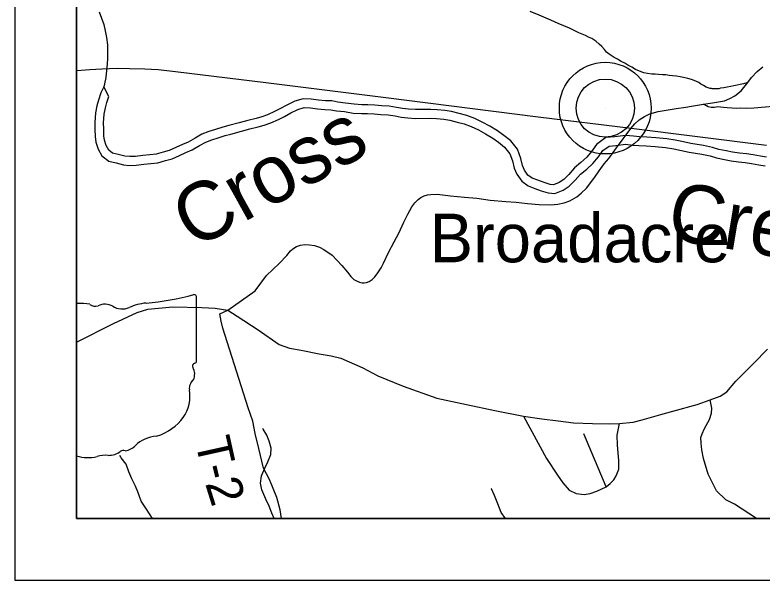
# Model space of a CAD drawing. Extents: x 0 to 34, y 0 to 22.
# Drawn here: x 2 to 3.211, y 14 to 14.917 of the extents above; entities that cross this region are included whole.
import ezdxf

# ---------------------------------------------------------------- set-up
doc = ezdxf.new("R2010")
doc.units = 0
for name, color, linetype in [('GM_X_Corporation', 7, 'Continuous'), ('GM_X_Corporation_Text', 7, 'Continuous'), ('GM_X_County_Road', 7, 'Continuous'), ('GM_X_Minor_River', 7, 'Continuous'), ('GM_X_Minor_River_Text', 7, 'Continuous'), ('GM_X_Rail_Line', 7, 'Continuous'), ('GM_X_State_Location', 7, 'Continuous'), ('GM_X_State_Route', 7, 'Continuous'), ('GM_X_Township_Road', 7, 'Continuous'), ('GM_X_Township_Road_Text', 7, 'Continuous'), ('GM_X_Unincorporated', 7, 'Continuous'), ('GM_X_Unincorporated_Location', 7, 'Continuous'), ('GM_X_Unincorporated_Text', 7, 'Continuous'), ('SH_Data', 7, 'Continuous')]:
    doc.layers.add(name, color=color, linetype=linetype)

msp = doc.modelspace()

# ---------------------------------------------------------------- linework, layer by layer
at = {"layer": 'GM_X_Corporation'}
msp.add_lwpolyline([(2.1, 15.7148), (2.1, 14.1), (4.5503, 14.1), (4.5507, 14.1138), (4.5505, 14.2449), (4.5614, 14.6695), (4.5616, 14.6767), (4.5617, 14.6817), (4.5685, 14.9157), (4.5738, 15.1325), (4.5873, 15.6794), (4.2138, 15.6834), (3.9277, 15.6898), (3.3171, 15.6975), (2.4078, 15.7088)], close=True, dxfattribs=at)
at = {"layer": 'GM_X_Corporation_Text'}
msp.add_line((2.1, 14.4488), (2.1, 14.2016), dxfattribs=at)
msp.add_lwpolyline([(2.2942, 14.3551), (2.2942, 14.3551), (2.2943, 14.3551), (2.2943, 14.4599)], dxfattribs=at)
for centre, major_axis, start_param, end_param in [((2.1769, 14.7276), (0.3495, 0), 4.814394, 5.042369), ((2.2906, 14.4602), (0.00367, 0), 6.197627, 7.989034), ((2.0997, 14.3425), (0.133, 0), 1.404758, 1.568575), ((2.1299, 14.4528), (0.0107, 0), 3.836095, 5.185415), ((2.1456, 14.4297), (0.0222, 0), 0.950623, 2.079405), ((2.1742, 14.4614), (0.0267, 0), 4.08156, 5.145723), ((2.2214, 14.3937), (0.0703, 0), 1.699012, 2.107814), ((2.2903, 14.3547), (0.00393, 0), 5.05454, 6.418171), ((2.2934, 14.3474), (0.00568, 0), 1.883978, 3.671073), ((2.2573, 14.3342), (0.0341, 0), 5.934695, 6.695948), ((2.3074, 14.3113), (0.0248, 0), 2.387724, 3.262537), ((2.1964, 14.298), (0.0874, 0), 5.101753, 6.440018), ((2.2333, 14.1951), (0.0479, 0), 1.647645, 2.488434), ((2.1517, 14.2237), (0.0267, 0), 4.691044, 5.507374), ((2.1758, 14.2043), (0.00752, 0), 1.147584, 2.315152), ((2.1726, 14.2318), (0.0282, 0), 4.937069, 5.64225), ((2.1191, 14.2387), (0.0501, 0), 4.321997, 4.996735), ((2.148, 14.1695), (0.0412, 0), 1.495662, 1.94098)]:
    msp.add_ellipse(centre, major_axis=major_axis, ratio=0.8, start_param=start_param, end_param=end_param, dxfattribs=at)
at = {"layer": 'GM_X_County_Road'}
msp.add_lwpolyline([(2.3454, 14.4378), (2.3601, 14.4281), (2.3945, 14.4061), (2.4283, 14.3823), (2.4453, 14.376), (2.4639, 14.3731), (2.4933, 14.3669), (2.5127, 14.364), (2.5285, 14.3598), (2.564, 14.3445), (2.5885, 14.3313), (2.6295, 14.3148), (2.684, 14.2954), (2.7321, 14.2849), (2.778, 14.2753), (2.8244, 14.2661), (2.8542, 14.2617), (2.8807, 14.2581), (2.9054, 14.2552), (2.9361, 14.2539), (2.9642, 14.2535), (2.98, 14.2543), (3.0024, 14.2561), (3.0169, 14.2598), (3.047, 14.2684), (3.0663, 14.2743), (3.1062, 14.2851), (3.1273, 14.2926), (3.1433, 14.2985), (3.1539, 14.3055), (3.1685, 14.3229), (3.1975, 14.3515), (3.2202, 14.3744)], dxfattribs=at)
at = {"layer": 'GM_X_Minor_River'}
for points in [[(2.1368, 14.9222), (2.1404, 14.9119), (2.1439, 14.9013), (2.1462, 14.8911), (2.1486, 14.8801), (2.1498, 14.8683), (2.15, 14.847), (2.1497, 14.8368), (2.1487, 14.8269), (2.1473, 14.8155), (2.1454, 14.8052), (2.1443, 14.8002)], [(2.1443, 14.8002), (2.1391, 14.7903), (2.1354, 14.7789), (2.1328, 14.7694), (2.1306, 14.7579), (2.1293, 14.7424), (2.1297, 14.7313), (2.1298, 14.7199), (2.1311, 14.7105), (2.135, 14.6991), (2.1411, 14.6881), (2.1522, 14.6795), (2.164, 14.6769), (2.1758, 14.6739), (2.1853, 14.6729), (2.1963, 14.673), (2.2092, 14.6746), (2.2202, 14.6758), (2.2316, 14.677), (2.2441, 14.6805), (2.2551, 14.6837), (2.2669, 14.6891), (2.2771, 14.6937), (2.2873, 14.698), (2.2994, 14.7049), (2.3092, 14.7107), (2.3191, 14.7142), (2.3297, 14.7177), (2.3407, 14.7212), (2.3501, 14.7236), (2.3672, 14.7282), (2.3808, 14.7322), (2.3945, 14.7353), (2.4043, 14.738), (2.415, 14.7419), (2.4271, 14.7473), (2.4369, 14.7524), (2.4475, 14.7581), (2.4588, 14.7635), (2.4691, 14.7667), (2.479, 14.766), (2.4907, 14.7646), (2.5025, 14.7635), (2.512, 14.7632), (2.5215, 14.7614), (2.5341, 14.76), (2.5482, 14.7578), (2.5618, 14.7568), (2.5717, 14.7568), (2.5824, 14.7562), (2.5934, 14.7555), (2.6052, 14.7548), (2.6162, 14.753), (2.6261, 14.7512), (2.6367, 14.7498), (2.6493, 14.7491), (2.674, 14.7493), (2.6835, 14.749), (2.6953, 14.7479), (2.7048, 14.7461), (2.717, 14.7432), (2.7284, 14.7402), (2.7398, 14.7358), (2.7513, 14.7305), (2.7627, 14.7242), (2.7746, 14.717), (2.7841, 14.7103), (2.7937, 14.7024), (2.8025, 14.6918), (2.8068, 14.68), (2.8095, 14.6683), (2.8134, 14.6584), (2.8215, 14.6471), (2.8318, 14.6396), (2.8429, 14.6355), (2.8532, 14.6318), (2.8646, 14.6281), (2.8752, 14.627), (2.8889, 14.6324), (2.8987, 14.639), (2.9081, 14.6486), (2.9168, 14.6585), (2.9269, 14.6666), (2.9371, 14.6761), (2.9461, 14.6865), (2.9533, 14.6968), (2.9635, 14.7041), (2.9741, 14.7053), (2.99, 14.707), (3.0018, 14.7059), (3.0117, 14.7052), (3.0235, 14.7046), (3.0379, 14.7036), (3.0547, 14.7018), (3.068, 14.6996), (3.0805, 14.6971), (3.0931, 14.6941), (3.1136, 14.6912), (3.127, 14.6883), (3.1376, 14.685), (3.1502, 14.6824)], [(3.153, 14.6963), (3.1412, 14.6987), (3.1306, 14.702), (3.1162, 14.7052), (3.0957, 14.7081), (3.0836, 14.7109), (3.0705, 14.7136), (3.0566, 14.7159), (3.0392, 14.7177), (3.0244, 14.7187), (3.0126, 14.7194), (3.0029, 14.7201), (2.9899, 14.7212), (2.9726, 14.7194), (2.9582, 14.7178), (2.943, 14.7069), (2.9349, 14.6952), (2.9269, 14.686), (2.9176, 14.6773), (2.9069, 14.6688), (2.8977, 14.6582), (2.8896, 14.65), (2.8822, 14.6451), (2.8732, 14.6415), (2.8675, 14.642), (2.8578, 14.6452), (2.8478, 14.6488), (2.8386, 14.6522), (2.8317, 14.6572), (2.826, 14.6653), (2.8231, 14.6725), (2.8204, 14.6841), (2.815, 14.699), (2.8037, 14.7125), (2.7927, 14.7215), (2.7823, 14.7289), (2.7698, 14.7364), (2.7577, 14.7432), (2.7454, 14.7488), (2.7328, 14.7538), (2.7204, 14.757), (2.7078, 14.76), (2.6972, 14.762), (2.6843, 14.7632), (2.6741, 14.7635), (2.6496, 14.7633), (2.6381, 14.7639), (2.6283, 14.7652), (2.6186, 14.767), (2.6067, 14.769), (2.5942, 14.7697), (2.5832, 14.7703), (2.5721, 14.771), (2.5623, 14.771), (2.5498, 14.7719), (2.536, 14.774), (2.5237, 14.7754), (2.5136, 14.7774), (2.5034, 14.7777), (2.4922, 14.7787), (2.4803, 14.7801), (2.4674, 14.781), (2.4537, 14.7768), (2.441, 14.7708), (2.4303, 14.7649), (2.4209, 14.7601), (2.4096, 14.7551), (2.4, 14.7516), (2.391, 14.7491), (2.3773, 14.7459), (2.3634, 14.7419), (2.3465, 14.7373), (2.3368, 14.7349), (2.3253, 14.7312), (2.3145, 14.7276), (2.3032, 14.7236), (2.2923, 14.7172), (2.281, 14.7107), (2.2714, 14.7067), (2.2609, 14.702), (2.2502, 14.697), (2.2403, 14.6942), (2.2289, 14.691), (2.2187, 14.6899), (2.2076, 14.6887), (2.1954, 14.6871), (2.1861, 14.6871), (2.1783, 14.6879), (2.1672, 14.6907), (2.1584, 14.6926), (2.1521, 14.6975), (2.148, 14.7049), (2.145, 14.7137), (2.144, 14.7209), (2.1439, 14.7317), (2.1435, 14.742), (2.1447, 14.756), (2.1467, 14.7662), (2.149, 14.7748), (2.1523, 14.7848), (2.1443, 14.8002)], [(3.2184, 14.6859), (3.2087, 14.6877), (3.1966, 14.6899), (3.1859, 14.6914), (3.1748, 14.6929), (3.1635, 14.6943), (3.153, 14.6963)], [(3.1502, 14.6824), (3.1612, 14.6802), (3.173, 14.6788), (3.184, 14.6774), (3.1943, 14.6759), (3.2061, 14.6737), (3.216, 14.6719)], [(2.4205, 14.1), (2.4162, 14.1088), (2.4119, 14.1198), (2.4065, 14.1312), (2.4003, 14.1463), (2.3983, 14.157), (2.3997, 14.1691), (2.4053, 14.1813), (2.4098, 14.192), (2.415, 14.2035), (2.4153, 14.2141), (2.4121, 14.2251), (2.4083, 14.2349), (2.4025, 14.2448), (2.4017, 14.2459)], [(2.2232, 14.1), (2.2133, 14.1149), (2.2044, 14.1281), (2.199, 14.1429), (2.1955, 14.1523), (2.1893, 14.1645), (2.1846, 14.1754), (2.1803, 14.1883), (2.1723, 14.1981), (2.17, 14.2019)], [(2.7953, 14.1), (2.7885, 14.1095), (2.783, 14.1235), (2.7776, 14.1372), (2.7726, 14.1481), (2.7722, 14.1485)]]:
    msp.add_lwpolyline(points, dxfattribs=at)
at = {"layer": 'GM_X_Rail_Line'}
msp.add_lwpolyline([(3.2186, 14.7051), (2.9988, 14.7325), (2.8485, 14.7513), (2.5972, 14.7827), (2.4066, 14.8066), (2.2601, 14.8247), (2.2321, 14.8276), (2.2108, 14.8288), (2.1859, 14.8297), (2.1658, 14.8299), (2.141, 14.8292), (2.1215, 14.828), (2.1071, 14.8268), (2.1, 14.8261)], dxfattribs=at)
at = {"layer": 'GM_X_State_Route'}
for points in [[(3.1881, 14.8075), (3.1942, 14.8152), (3.2035, 14.8253), (3.2124, 14.8329)], [(3.1165, 14.772), (3.1307, 14.7741), (3.1501, 14.7778), (3.1589, 14.7812), (3.1671, 14.7858), (3.1771, 14.7938), (3.1881, 14.8075)], [(2.9401, 14.6537), (2.9474, 14.664), (2.9554, 14.6755), (2.9627, 14.684), (2.9752, 14.7014), (2.9985, 14.7327), (3.0048, 14.7403), (3.0121, 14.7467), (3.0204, 14.7522), (3.0294, 14.7566), (3.043, 14.7603), (3.0722, 14.765), (3.0876, 14.7674)], [(3.0876, 14.7674), (3.0966, 14.7691), (3.1165, 14.772)], [(2.3454, 14.4378), (2.3894, 14.4691), (2.408, 14.4943), (2.4283, 14.5138), (2.4407, 14.5266), (2.4467, 14.534), (2.4505, 14.5374), (2.4567, 14.5412), (2.4628, 14.5432), (2.4698, 14.5444), (2.4776, 14.544), (2.4858, 14.5427), (2.4935, 14.54), (2.5005, 14.5366), (2.5141, 14.5273), (2.5301, 14.5105), (2.5394, 14.4998), (2.5446, 14.4925), (2.5493, 14.4878), (2.5549, 14.4848), (2.5588, 14.4832), (2.5628, 14.4822), (2.5664, 14.4823), (2.5699, 14.483), (2.5744, 14.4846), (2.5791, 14.4876), (2.5832, 14.4919), (2.5874, 14.497), (2.5938, 14.5067), (2.5976, 14.5143), (2.6058, 14.5314), (2.6147, 14.549), (2.6221, 14.5628), (2.6306, 14.5807), (2.6372, 14.5935), (2.6436, 14.6058), (2.6481, 14.6118), (2.6538, 14.6173), (2.658, 14.6207), (2.6635, 14.6232), (2.6687, 14.6249), (2.6742, 14.6258), (2.6846, 14.6259), (2.7063, 14.6235), (2.7289, 14.6212), (2.7489, 14.6194), (2.7706, 14.6166), (2.7959, 14.6142), (2.8127, 14.6129), (2.8307, 14.6111), (2.8496, 14.6092), (2.8681, 14.6086), (2.8802, 14.6097), (2.8902, 14.6119), (2.8998, 14.6155), (2.9108, 14.622), (2.918, 14.6276), (2.9266, 14.636), (2.9384, 14.6513), (2.9401, 14.6537)], [(2.1, 14.3858), (2.1598, 14.4163), (2.1983, 14.4343), (2.2155, 14.4394), (2.2562, 14.4434), (2.3032, 14.4423), (2.3247, 14.4411), (2.3454, 14.4378)]]:
    msp.add_lwpolyline(points, dxfattribs=at)
at = {"layer": 'GM_X_Township_Road'}
msp.add_line((2.9583, 14.1514), (2.9223, 14.2374), dxfattribs=at)
for points in [[(3.1291, 14.7974), (3.1273, 14.7977), (3.1254, 14.7982), (3.1204, 14.8), (3.1164, 14.8024), (3.112, 14.8048), (3.1085, 14.8074), (3.105, 14.809), (3.1012, 14.8107), (3.0966, 14.8121), (3.0907, 14.8138), (3.0841, 14.8153), (3.0786, 14.8167), (3.0724, 14.8176), (3.0661, 14.8182), (3.0608, 14.8189), (3.0553, 14.8195), (3.05, 14.8197), (3.0434, 14.8202), (3.0377, 14.8208), (3.0324, 14.8208), (3.0256, 14.8217), (3.0193, 14.8232), (3.0126, 14.8257), (3.0063, 14.8285), (3.0001, 14.8323), (2.9935, 14.8356), (2.9887, 14.8386), (2.9828, 14.8413), (2.977, 14.8452), (2.9717, 14.8477), (2.9636, 14.8532), (2.9592, 14.8567), (2.9559, 14.8608), (2.9515, 14.8655), (2.9471, 14.8697), (2.9418, 14.8741), (2.935, 14.8785), (2.93, 14.8809), (2.9251, 14.8835), (2.9142, 14.8879), (2.8988, 14.8954), (2.8809, 14.9031), (2.8686, 14.9084), (2.8499, 14.9165), (2.8355, 14.9226)], [(3.1165, 14.772), (3.1307, 14.7741), (3.1501, 14.7778), (3.1589, 14.7812), (3.1671, 14.7858), (3.1771, 14.7938), (3.1881, 14.8075)], [(3.1881, 14.8075), (3.1813, 14.805), (3.1756, 14.8039), (3.1711, 14.803), (3.1654, 14.8019), (3.1604, 14.8008), (3.1549, 14.7997), (3.1492, 14.7984), (3.1437, 14.798), (3.1409, 14.7973), (3.1386, 14.7971), (3.1345, 14.7972), (3.1301, 14.7973), (3.1291, 14.7974)], [(3.229, 14.7683), (3.198, 14.7657), (3.1854, 14.7652), (3.1766, 14.7654), (3.1694, 14.7652), (3.1621, 14.7657), (3.1547, 14.7663), (3.1487, 14.7668), (3.1441, 14.7674), (3.1393, 14.7676), (3.1342, 14.767), (3.1285, 14.7668), (3.1241, 14.7676), (3.121, 14.7694), (3.1165, 14.772)], [(2.432, 14.1), (2.4299, 14.114), (2.4246, 14.1341), (2.4128, 14.1634), (2.403, 14.1815), (2.3953, 14.2136), (2.3896, 14.2377), (2.3855, 14.2578), (2.378, 14.2793), (2.3368, 14.4089), (2.3343, 14.4199), (2.3322, 14.432), (2.3454, 14.4378)], [(3.2022, 14.1), (3.1668, 14.1234), (3.1527, 14.1303), (3.1375, 14.145), (3.124, 14.172), (3.1165, 14.1972), (3.1135, 14.2112), (3.1123, 14.2223), (3.1121, 14.2311), (3.1139, 14.2374), (3.1179, 14.2458), (3.1258, 14.2603), (3.1291, 14.2709), (3.1298, 14.2788), (3.1273, 14.2926)], [(2.8244, 14.2661), (2.8615, 14.1972), (2.8794, 14.1702), (2.888, 14.1576), (2.8985, 14.1458), (2.9096, 14.1404), (2.9229, 14.1391), (2.9323, 14.1403), (2.9436, 14.144), (2.9583, 14.1514), (2.965, 14.1565), (2.9709, 14.1629), (2.9749, 14.1692), (2.9792, 14.1797), (2.9792, 14.194), (2.977, 14.219), (2.9764, 14.2353), (2.98, 14.2543)]]:
    msp.add_lwpolyline(points, dxfattribs=at)
at = {"layer": 'GM_X_Unincorporated'}
for radius in [0.0744, 0.0472]:
    msp.add_circle((2.957, 14.7657), radius, dxfattribs=at)
at = {"layer": 'GM_X_Unincorporated_Location'}
msp.add_line((2.957, 14.7657), (2.957, 14.7657), dxfattribs=at)
at = {"layer": 'SH_Data'}
for p, q in [((2, 21), (2, 14)), ((2, 14), (9, 14))]:
    msp.add_line(p, q, dxfattribs=at)
msp.add_lwpolyline([(2.1, 20.9), (8.9, 20.9), (8.9, 14.1), (2.1, 14.1)], close=True, dxfattribs=at)

# ---------------------------------------------------------------- texts
at = {"layer": 'GM_X_Minor_River_Text'}
for s, height, rotation, p in [('Cross', 0.09468, 29.027, (2.29, 14.5353)), ('Creek', 0.0947, 350.5621, (3.0543, 14.5542))]:
    msp.add_text(s, height=height, rotation=rotation, dxfattribs=at).set_placement(p)
at = {"layer": 'GM_X_State_Location'}
for s in ['s', 'r']:
    msp.add_text(s, height=0.000189, dxfattribs=at).set_placement((2.1258, 14.338))
at = {"layer": 'GM_X_Township_Road_Text'}
for s, rotation, p in [('T', 282.5414, (2.2918, 14.2261)), ('-', 284.0047, (2.3014, 14.1831)), ('2', 287.3259, (2.308, 14.157))]:
    msp.add_text(s, height=0.0568, rotation=rotation, dxfattribs=at).set_placement(p)
at = {"layer": 'GM_X_Unincorporated_Text'}
msp.add_text('Broadacre', height=0.07898, rotation=0, dxfattribs=at).set_placement((2.6722, 14.5156))

doc.saveas('drawing.dxf')
